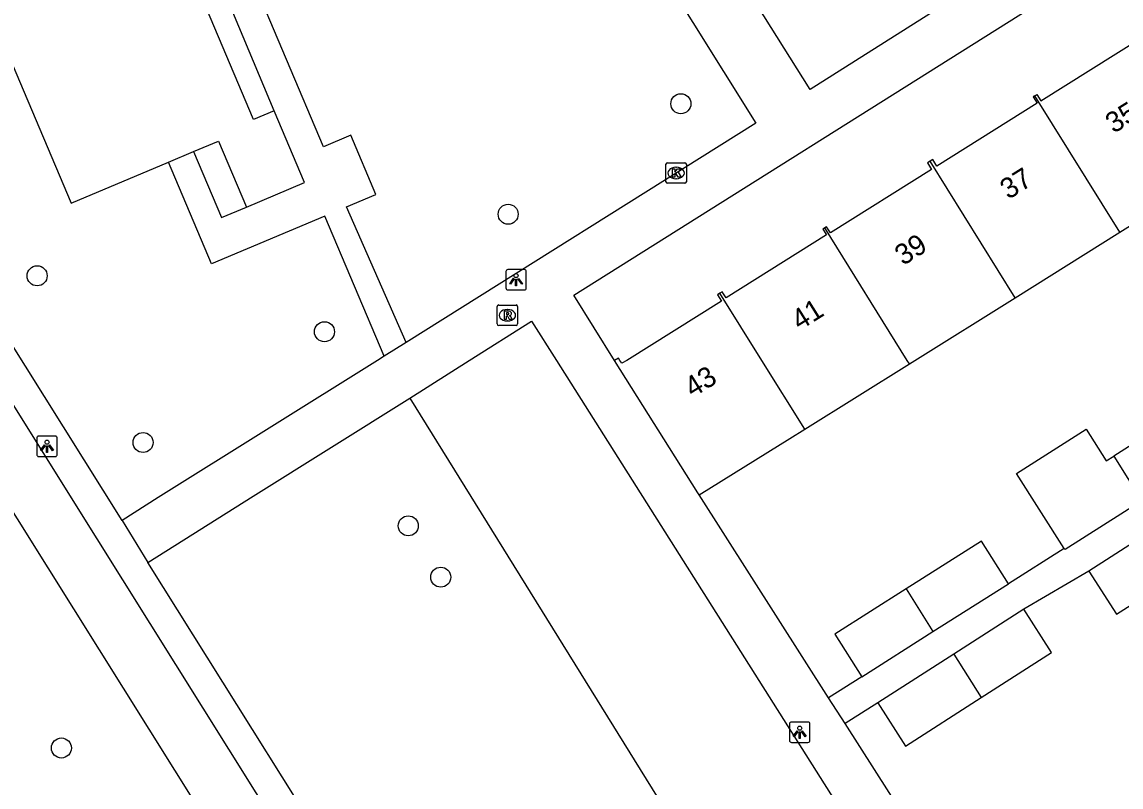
# Model space of a CAD drawing. Extents: x 160077 to 160945, y 386481 to 387498.
# Drawn here: x 160308.2 to 160361.9, y 386979.2 to 387016.5 of the extents above; entities that cross this region are included whole.
import ezdxf

# ---------------------------------------------------------------- set-up
doc = ezdxf.new("R2010")
doc.units = 0
for name, color, linetype in [('IMGEO_Boom', 7, 'Continuous'), ('IMGEO_Fietspad_gesloten', 7, 'Continuous'), ('IMGEO_Groenvoorziening', 7, 'Continuous'), ('IMGEO_Kolk', 7, 'Continuous'), ('IMGEO_Lichtpunt', 7, 'Continuous'), ('IMGEO_Pand', 7, 'Continuous'), ('IMGEO_Pand_nummerreeks', 7, 'Continuous'), ('IMGEO_Rioolput', 7, 'Continuous'), ('IMGEO_Voetpad_open', 7, 'Continuous')]:
    doc.layers.add(name, color=color, linetype=linetype)

msp = doc.modelspace()

# ---------------------------------------------------------------- linework, layer by layer
at = {"layer": 'IMGEO_Boom'}
for centre in [(160340.385, 387012.55), (160331.946, 387007.15), (160308.936, 387004.143), (160322.972, 387001.41), (160314.11, 386995.998), (160327.068, 386991.929), (160328.652, 386989.421), (160310.12, 386981.074)]:
    msp.add_circle(centre, 0.489, dxfattribs=at)
at = {"layer": 'IMGEO_Fietspad_gesloten'}
for points in [[(160300.054, 387010.149), (160311.846, 386991.299), (160336.414, 386952.059), (160340.267, 386945.91)], [(160298.634, 387007.207), (160300.211, 387004.626), (160309.459, 386989.877), (160320.577, 386972.116), (160331.8, 386954.187), (160333.952, 386950.749), (160340.92, 386939.644), (160352.34, 386921.431), (160362.991, 386904.447), (160373.722, 386887.333), (160381.199, 386875.409), (160381.719, 386874.568), (160381.755, 386874.497)]]:
    msp.add_lwpolyline(points, dxfattribs=at)
at = {"layer": 'IMGEO_Groenvoorziening'}
msp.add_lwpolyline([(160327.145, 386998.17), (160353.425, 386955.793)], dxfattribs=at)
at = {"layer": 'IMGEO_Kolk'}
for p, q in [((160339.652, 387008.738), (160339.652, 387009.59)), ((160339.727, 387009.664), (160340.579, 387009.664)), ((160340.653, 387009.59), (160340.653, 387008.738)), ((160340.14, 387009.444), (160340.165, 387009.444)), ((160340.579, 387008.664), (160339.727, 387008.664)), ((160340.163, 387008.884), (160340.138, 387008.884))]:
    msp.add_line(p, q, dxfattribs=at)
for points in [[(160339.652, 387008.738), (160339.652, 387009.59)], [(160339.727, 387009.664), (160340.579, 387009.664)], [(160340.653, 387009.59), (160340.653, 387008.738)], [(160339.973, 387009.364), (160340.096, 387009.364), (160340.096, 387009.213), (160340.226, 387009.364), (160340.39, 387009.364), (160340.244, 387009.213), (160340.397, 387008.964), (160340.245, 387008.964), (160340.16, 387009.128), (160340.096, 387009.061), (160340.096, 387008.964), (160339.973, 387008.964), (160339.973, 387009.364)], [(160340.579, 387008.664), (160339.727, 387008.664)]]:
    msp.add_lwpolyline(points, dxfattribs=at)
for centre, start, end in [((160339.729, 387009.588), 91.552, 178.448), ((160339.729, 387009.588), 91.552, 178.448), ((160340.577, 387009.588), 1.552, 88.448), ((160340.577, 387009.588), 1.552, 88.448), ((160339.729, 387008.74), 181.552, 268.448), ((160339.729, 387008.74), 181.552, 268.448), ((160340.577, 387008.74), 271.552, 358.448), ((160340.577, 387008.74), 271.552, 358.448)]:
    msp.add_arc(centre, 0.0765, start, end, dxfattribs=at)
for centre, major_axis, ratio, start_param, end_param in [((160340.139, 387009.164), (-0.387, 0.002), 0.722429, 4.712389, 7.853982), ((160340.164, 387009.164), (-0.39, 0.002), 0.717154, 1.570796, 4.712389)]:
    msp.add_ellipse(centre, major_axis=major_axis, ratio=ratio, start_param=start_param, end_param=end_param, dxfattribs=at)
at = {"layer": 'IMGEO_Lichtpunt'}
for p, q in [((160331.835, 387004.355), (160331.835, 387003.548)), ((160331.835, 387004.355), (160331.835, 387003.548)), ((160332.737, 387004.45), (160331.929, 387004.45)), ((160332.737, 387004.45), (160331.929, 387004.45)), ((160332.831, 387003.548), (160332.831, 387004.355)), ((160332.831, 387003.548), (160332.831, 387004.355)), ((160331.929, 387003.454), (160332.737, 387003.454)), ((160331.929, 387003.454), (160332.737, 387003.454)), ((160308.921, 386996.216), (160308.921, 386995.409)), ((160308.921, 386996.216), (160308.921, 386995.409)), ((160309.823, 386996.311), (160309.015, 386996.311)), ((160309.823, 386996.311), (160309.015, 386996.311)), ((160309.917, 386995.409), (160309.917, 386996.216)), ((160309.917, 386995.409), (160309.917, 386996.216)), ((160309.015, 386995.315), (160309.823, 386995.315)), ((160309.015, 386995.315), (160309.823, 386995.315)), ((160345.691, 386982.246), (160345.691, 386981.439)), ((160345.691, 386982.246), (160345.691, 386981.439)), ((160346.593, 386982.341), (160345.785, 386982.341)), ((160346.593, 386982.341), (160345.785, 386982.341)), ((160346.687, 386981.439), (160346.687, 386982.246)), ((160346.687, 386981.439), (160346.687, 386982.246)), ((160345.785, 386981.345), (160346.593, 386981.345)), ((160345.785, 386981.345), (160346.593, 386981.345))]:
    msp.add_line(p, q, dxfattribs=at)
for points in [[(160332.209, 387004.019), (160332.248, 387003.991), (160332.06, 387003.729), (160332.022, 387003.756), (160332.209, 387004.019)], [(160332.311, 387003.971), (160332.358, 387003.971), (160332.358, 387003.649), (160332.311, 387003.649), (160332.311, 387003.971)], [(160332.421, 387003.991), (160332.459, 387004.018), (160332.646, 387003.756), (160332.607, 387003.728), (160332.421, 387003.991)], [(160309.295, 386995.88), (160309.334, 386995.852), (160309.146, 386995.59), (160309.108, 386995.617), (160309.295, 386995.88)], [(160309.397, 386995.832), (160309.444, 386995.832), (160309.444, 386995.51), (160309.397, 386995.51), (160309.397, 386995.832)], [(160309.507, 386995.852), (160309.545, 386995.879), (160309.732, 386995.617), (160309.693, 386995.589), (160309.507, 386995.852)], [(160346.065, 386981.91), (160346.104, 386981.882), (160345.916, 386981.62), (160345.878, 386981.647), (160346.065, 386981.91)], [(160346.167, 386981.862), (160346.214, 386981.862), (160346.214, 386981.54), (160346.167, 386981.54), (160346.167, 386981.862)], [(160346.277, 386981.882), (160346.315, 386981.909), (160346.502, 386981.647), (160346.463, 386981.619), (160346.277, 386981.882)]]:
    msp.add_lwpolyline(points, dxfattribs=at)
for centre in [(160332.334, 387004.153), (160309.42, 386996.014), (160346.19, 386982.044)]:
    msp.add_circle(centre, 0.0994, dxfattribs=at)
for centre, start, end in [((160331.929, 387004.355), 90, 180), ((160331.929, 387004.355), 90, 180), ((160332.737, 387004.355), 0, 90), ((160332.737, 387004.355), 0, 90), ((160331.929, 387003.548), 180, 270), ((160331.929, 387003.548), 180, 270), ((160332.737, 387003.548), 270, 0), ((160332.737, 387003.548), 270, 360), ((160309.015, 386996.216), 90, 180), ((160309.015, 386996.216), 90, 180), ((160309.823, 386996.216), 0, 90), ((160309.823, 386996.216), 0, 90), ((160309.015, 386995.409), 180, 270), ((160309.015, 386995.409), 180, 270), ((160309.823, 386995.409), 270, 0), ((160309.823, 386995.409), 270, 360), ((160345.785, 386982.246), 90, 180), ((160345.785, 386982.246), 90, 180), ((160346.593, 386982.246), 0, 90), ((160346.593, 386982.246), 0, 90), ((160345.785, 386981.439), 180, 270), ((160345.785, 386981.439), 180, 270), ((160346.593, 386981.439), 270, 0), ((160346.593, 386981.439), 270, 360)]:
    msp.add_arc(centre, 0.0946, start, end, dxfattribs=at)
at = {"layer": 'IMGEO_Pand'}
for points in [[(160298.298, 387071.04), (160297.928, 387070.885), (160298.035, 387070.627), (160296.023, 387069.791), (160296.357, 387068.987), (160291.051, 387066.783), (160289.805, 387069.781), (160281.799, 387066.389), (160285.315, 387058.089), (160288.652, 387059.502), (160310.605, 387007.683), (160315.35, 387009.693)], [(160320.521, 387012.204), (160319.506, 387011.774), (160297.664, 387063.334), (160298.877, 387063.837)], [(160357.68, 387012.938), (160357.771, 387012.995), (160357.965, 387012.684), (160362.85, 387015.744), (160362.65, 387016.062), (160362.78, 387016.143)], [(160357.68, 387012.938), (160357.591, 387012.882), (160357.787, 387012.57), (160352.893, 387009.505), (160352.696, 387009.819), (160352.565, 387009.738)], [(160361.83, 387006.275), (160357.68, 387012.938)], [(160319.158, 387007.502), (160322.002, 387008.707), (160320.521, 387012.204)], [(160316.58, 387010.214), (160317.792, 387010.727), (160319.158, 387007.502)], [(160315.35, 387009.693), (160316.58, 387010.214)], [(160352.565, 387009.738), (160352.433, 387009.655), (160352.632, 387009.337), (160347.691, 387006.242), (160347.506, 387006.537), (160347.412, 387006.478)], [(160356.717, 387003.073), (160352.565, 387009.738)], [(160361.83, 387006.275), (160366.936, 387009.473)], [(160347.412, 387006.478), (160347.321, 387006.421), (160347.498, 387006.138), (160342.593, 387003.065), (160342.408, 387003.361), (160342.295, 387003.291)], [(160351.549, 386999.836), (160351.447, 387000), (160347.412, 387006.478)], [(160356.717, 387003.073), (160361.83, 387006.275)], [(160342.295, 387003.291), (160342.178, 387003.218), (160342.374, 387002.906), (160337.739, 387000.002), (160337.492, 386999.872), (160337.407, 387000), (160337.331, 387000.12), (160337.144, 387000)], [(160346.433, 386996.648), (160344.345, 387000), (160342.295, 387003.291)], [(160351.549, 386999.836), (160351.812, 387000), (160356.717, 387003.073)], [(160341.28, 386993.441), (160341.218, 386993.539), (160337.144, 387000)], [(160346.433, 386996.648), (160351.549, 386999.836)], [(160366.769, 386995.617), (160365.39, 386997.785), (160361.538, 386995.334)], [(160341.28, 386993.441), (160345.71, 386996.198), (160346.433, 386996.648)], [(160359.115, 386990.826), (160356.787, 386994.483), (160360.185, 386996.645), (160361.169, 386995.099), (160361.538, 386995.334)], [(160361.538, 386995.334), (160362.897, 386993.153)], [(160362.897, 386993.153), (160359.151, 386990.769), (160359.115, 386990.826)], [(160364.038, 386992.103), (160360.313, 386989.716)], [(160356.384, 386989.096), (160355.069, 386991.173), (160351.394, 386988.846)], [(160360.313, 386989.716), (160361.665, 386987.605), (160365.372, 386989.98)], [(160352.694, 386986.759), (160356.384, 386989.096)], [(160351.394, 386988.846), (160347.904, 386986.636), (160349.219, 386984.559)], [(160351.394, 386988.846), (160352.694, 386986.759)], [(160357.14, 386987.85), (160353.725, 386985.662)], [(160355.059, 386983.539), (160358.492, 386985.738), (160357.14, 386987.85)], [(160349.219, 386984.559), (160352.694, 386986.759)], [(160353.725, 386985.662), (160349.999, 386983.275)], [(160353.725, 386985.662), (160355.059, 386983.539)], [(160349.999, 386983.275), (160351.351, 386981.164), (160355.059, 386983.539)]]:
    msp.add_lwpolyline(points, dxfattribs=at)
at = {"layer": 'IMGEO_Rioolput'}
for p, q in [((160331.409, 387001.79), (160331.409, 387002.642)), ((160331.484, 387002.716), (160332.336, 387002.716)), ((160332.41, 387002.642), (160332.41, 387001.79)), ((160331.897, 387002.496), (160331.922, 387002.496)), ((160332.336, 387001.716), (160331.484, 387001.716)), ((160331.92, 387001.936), (160331.895, 387001.936))]:
    msp.add_line(p, q, dxfattribs=at)
for points in [[(160331.409, 387001.79), (160331.409, 387002.642)], [(160331.484, 387002.716), (160332.336, 387002.716)], [(160332.41, 387002.642), (160332.41, 387001.79)], [(160331.998, 387002.414), (160331.746, 387002.416), (160331.746, 387002.016)], [(160331.746, 387002.016), (160331.87, 387002.016), (160331.87, 387002.178), (160331.881, 387002.178)], [(160331.924, 387002.335), (160331.87, 387002.335), (160331.87, 387002.254)], [(160331.87, 387002.254), (160331.922, 387002.254)], [(160331.928, 387002.149), (160331.999, 387002.016), (160332.139, 387002.016), (160332.074, 387002.142)], [(160332.336, 387001.716), (160331.484, 387001.716)]]:
    msp.add_lwpolyline(points, dxfattribs=at)
for centre, radius, start, end in [((160331.486, 387002.64), 0.0765, 91.552, 178.448), ((160331.486, 387002.64), 0.0765, 91.552, 178.448), ((160332.334, 387002.64), 0.0765, 1.552, 88.448), ((160332.334, 387002.64), 0.0765, 1.552, 88.448), ((160331.88, 387002.125), 0.0533, 26.0293, 88.6989), ((160331.906, 387002.443), 0.19, 274.7715, 282.9687), ((160331.93, 387002.239), 0.0964, 77.0061, 93.1865), ((160331.944, 387002.296), 0.0378, 276.6634, 79.6772), ((160331.997, 387002.304), 0.109, 350.3612, 89.416), ((160331.995, 387002.304), 0.112, 277.5842, 350.9817), ((160331.979, 387002.089), 0.108, 29.5134, 73.7905), ((160331.486, 387001.792), 0.0765, 181.552, 268.448), ((160331.486, 387001.792), 0.0765, 181.552, 268.448), ((160332.334, 387001.792), 0.0765, 271.552, 358.448), ((160332.334, 387001.792), 0.0765, 271.552, 358.448)]:
    msp.add_arc(centre, radius, start, end, dxfattribs=at)
for centre, major_axis, ratio, start_param, end_param in [((160331.896, 387002.216), (-0.387, 0.002), 0.722429, 4.712389, 7.853982), ((160331.921, 387002.216), (-0.39, 0.002), 0.717154, 1.570796, 4.712389)]:
    msp.add_ellipse(centre, major_axis=major_axis, ratio=ratio, start_param=start_param, end_param=end_param, dxfattribs=at)
at = {"layer": 'IMGEO_Voetpad_open'}
for points in [[(160313.092, 386992.189), (160295.106, 387020.877), (160281.201, 387043.025), (160273.607, 387055.119), (160270.266, 387065.426), (160268.032, 387072.414)], [(160326.961, 387000.883), (160324.051, 387007.52), (160325.476, 387008.122), (160324.258, 387011.006), (160322.921, 387010.441), (160301.226, 387061.655), (160304.436, 387063.04), (160303.501, 387065.215), (160309.043, 387067.68)], [(160309.043, 387067.68), (160339.387, 387019.061), (160344.043, 387011.607), (160326.961, 387000.883)], [(160320.521, 387012.204), (160298.877, 387063.837)], [(160337.144, 387000), (160335.156, 387003.195), (160358.002, 387017.565)], [(160352.547, 387016.942), (160346.706, 387013.244), (160343.808, 387017.863)], [(160316.58, 387010.214), (160317.946, 387006.988), (160319.158, 387007.502)], [(160325.887, 387000.209), (160322.986, 387007.052), (160317.452, 387004.732), (160315.35, 387009.693)], [(160327.145, 386998.17), (160330.043, 387000), (160333.091, 387001.929), (160334.305, 387000.002), (160358.281, 386962.101)], [(160326.961, 387000.883), (160325.887, 387000.209)], [(160325.887, 387000.209), (160325.558, 387000.002), (160314.851, 386993.307), (160313.092, 386992.189)], [(160314.349, 386990.13), (160319.488, 386993.382), (160327.145, 386998.17)], [(160347.604, 386983.53), (160341.28, 386993.441)], [(160313.092, 386992.189), (160314.349, 386990.13)], [(160359.115, 386990.826), (160356.384, 386989.096)], [(160339.984, 386949.196), (160337.688, 386952.871), (160314.349, 386990.13)], [(160360.313, 386989.716), (160357.14, 386987.85)], [(160349.219, 386984.559), (160347.604, 386983.53)], [(160348.413, 386982.263), (160347.604, 386983.53)], [(160349.999, 386983.275), (160348.413, 386982.263)], [(160354.139, 386973.29), (160348.413, 386982.263)]]:
    msp.add_lwpolyline(points, dxfattribs=at)

# ---------------------------------------------------------------- texts
at = {"layer": 'IMGEO_Pand_nummerreeks'}
for s, rotation, p in [('35', 32.0993, (160361.531, 387011.072)), ('37', 32.0993, (160356.385, 387007.845)), ('39', 32.0993, (160351.24, 387004.617)), ('41', 32.0993, (160346.191, 387001.45)), ('43', 31.8622, (160340.963, 386998.167))]:
    msp.add_text(s, height=1, rotation=rotation, dxfattribs=at).set_placement(p)

doc.saveas('drawing.dxf')
